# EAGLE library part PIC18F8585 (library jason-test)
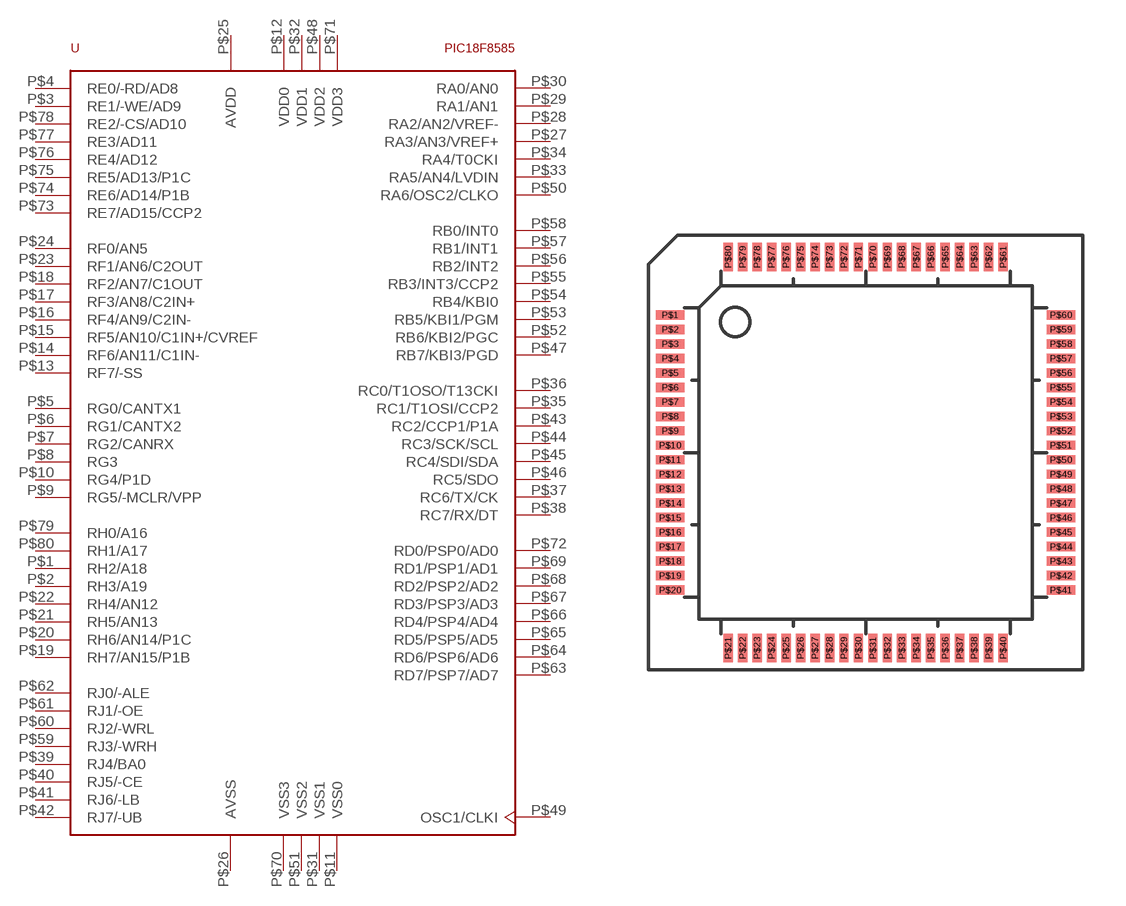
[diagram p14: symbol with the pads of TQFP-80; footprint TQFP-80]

Designator prefix -

## PIC18F8585  [TQFP-80]
P$1  RH2/A18
P$2  RH3/A19
P$3  RE1/-WE/AD9
P$4  RE0/-RD/AD8
P$5  RG0/CANTX1
P$6  RG1/CANTX2
P$7  RG2/CANRX
P$8  RG3
P$9  RG5/-MCLR/VPP
P$10  RG4/P1D
P$11  VSS0  pwr
P$12  VDD0  pwr
P$13  RF7/-SS
P$14  RF6/AN11/C1IN-
P$15  RF5/AN10/C1IN+/CVREF
P$16  RF4/AN9/C2IN-
P$17  RF3/AN8/C2IN+
P$18  RF2/AN7/C1OUT
P$19  RH7/AN15/P1B
P$20  RH6/AN14/P1C
P$21  RH5/AN13
P$22  RH4/AN12
P$23  RF1/AN6/C2OUT
P$24  RF0/AN5
P$25  AVDD  pwr
P$26  AVSS  pwr
P$27  RA3/AN3/VREF+
P$28  RA2/AN2/VREF-
P$29  RA1/AN1
P$30  RA0/AN0
P$31  VSS1  pwr
P$32  VDD1  pwr
P$33  RA5/AN4/LVDIN
P$34  RA4/T0CKI
P$35  RC1/T1OSI/CCP2
P$36  RC0/T1OSO/T13CKI
P$37  RC6/TX/CK
P$38  RC7/RX/DT
P$39  RJ4/BA0
P$40  RJ5/-CE
P$41  RJ6/-LB
P$42  RJ7/-UB
P$43  RC2/CCP1/P1A
P$44  RC3/SCK/SCL
P$45  RC4/SDI/SDA
P$46  RC5/SDO
P$47  RB7/KBI3/PGD
P$48  VDD2  pwr
P$49  OSC1/CLKI
P$50  RA6/OSC2/CLKO
P$51  VSS2  pwr
P$52  RB6/KBI2/PGC
P$53  RB5/KBI1/PGM
P$54  RB4/KBI0
P$55  RB3/INT3/CCP2
P$56  RB2/INT2
P$57  RB1/INT1
P$58  RB0/INT0
P$59  RJ3/-WRH
P$60  RJ2/-WRL
P$61  RJ1/-OE
P$62  RJ0/-ALE
P$63  RD7/PSP7/AD7
P$64  RD6/PSP6/AD6
P$65  RD5/PSP5/AD5
P$66  RD4/PSP4/AD4
P$67  RD3/PSP3/AD3
P$68  RD2/PSP2/AD2
P$69  RD1/PSP1/AD1
P$70  VSS3  pwr
P$71  VDD3  pwr
P$72  RD0/PSP0/AD0
P$73  RE7/AD15/CCP2
P$74  RE6/AD14/P1B
P$75  RE5/AD13/P1C
P$76  RE4/AD12
P$77  RE3/AD11
P$78  RE2/-CS/AD10
P$79  RH0/A16
P$80  RH1/A17

## Footprint TQFP-80 (pad centres in mm)
smd 1.016 x 0.33: P$1 -6.858,4.826; P$2 -6.858,4.318; P$3 -6.858,3.81; P$4 -6.858,3.302; P$5 -6.858,2.794; P$6 -6.858,2.286; P$7 -6.858,1.778; P$8 -6.858,1.27; P$9 -6.858,0.762; P$10 -6.858,0.254; P$11 -6.858,-0.254; P$12 -6.858,-0.762; P$13 -6.858,-1.27; P$14 -6.858,-1.778; P$15 -6.858,-2.286; P$16 -6.858,-2.794; P$17 -6.858,-3.302; P$18 -6.858,-3.81; P$19 -6.858,-4.318; P$20 -6.858,-4.826; P$41 6.858,-4.826; P$42 6.858,-4.318; P$43 6.858,-3.81; P$44 6.858,-3.302; P$45 6.858,-2.794; P$46 6.858,-2.286; P$47 6.858,-1.778; P$48 6.858,-1.27; P$49 6.858,-0.762; P$50 6.858,-0.254; P$51 6.858,0.254; P$52 6.858,0.762; P$53 6.858,1.27; P$54 6.858,1.778; P$55 6.858,2.286; P$56 6.858,2.794; P$57 6.858,3.302; P$58 6.858,3.81; P$59 6.858,4.318; P$60 6.858,4.826
smd 0.33 x 1.016: P$21 -4.826,-6.858; P$22 -4.318,-6.858; P$23 -3.81,-6.858; P$24 -3.302,-6.858; P$25 -2.794,-6.858; P$26 -2.286,-6.858; P$27 -1.778,-6.858; P$28 -1.27,-6.858; P$29 -0.762,-6.858; P$30 -0.254,-6.858; P$31 0.254,-6.858; P$32 0.762,-6.858; P$33 1.27,-6.858; P$34 1.778,-6.858; P$35 2.286,-6.858; P$36 2.794,-6.858; P$37 3.302,-6.858; P$38 3.81,-6.858; P$39 4.318,-6.858; P$40 4.826,-6.858; P$61 4.826,6.858; P$62 4.318,6.858; P$63 3.81,6.858; P$64 3.302,6.858; P$65 2.794,6.858; P$66 2.286,6.858; P$67 1.778,6.858; P$68 1.27,6.858; P$69 0.762,6.858; P$70 0.254,6.858; P$71 -0.254,6.858; P$72 -0.762,6.858; P$73 -1.27,6.858; P$74 -1.778,6.858; P$75 -2.286,6.858; P$76 -2.794,6.858; P$77 -3.302,6.858; P$78 -3.81,6.858; P$79 -4.318,6.858; P$80 -4.826,6.858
